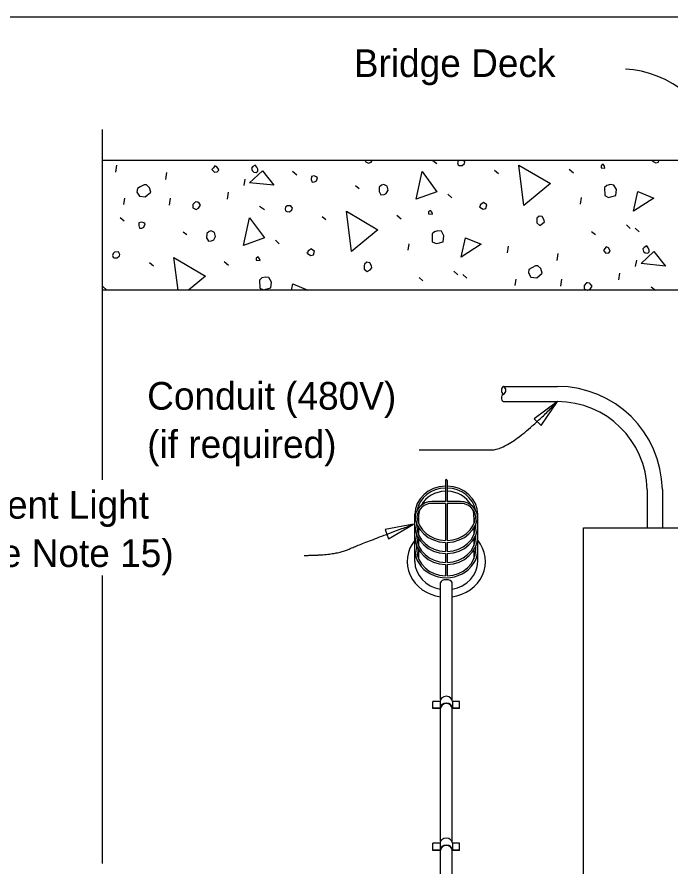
# Model space of a CAD drawing. Extents: x 112544 to 112597.1, y 111084 to 111107.1.
# Drawn here: x 112556.46 to 112560.031, y 111100.721 to 111105.363 of the extents above; entities that cross this region are included whole.
import ezdxf

# ---------------------------------------------------------------- set-up
doc = ezdxf.new("R2010")
doc.units = 0
for name, color, linetype in [('ActivePts-ConstElements', 7, 'Continuous'), ('Dimension', 7, 'Continuous'), ('Lighting', 7, 'Continuous'), ('Miscellaneous', 7, 'Continuous'), ('SteelGirder', 7, 'Continuous'), ('SupstrConc', 7, 'Continuous'), ('TextStructures', 7, 'Continuous')]:
    doc.layers.add(name, color=color, linetype=linetype)

msp = doc.modelspace()

# ---------------------------------------------------------------- linework, layer by layer
at = {"layer": 'ActivePts-ConstElements'}
msp.add_lwpolyline([(112543.9918, 111085.9039), (112574.7797, 111085.9039), (112574.7797, 111105.3634), (112543.9918, 111105.3634)], close=True, dxfattribs=at)
at = {"layer": 'Dimension'}
for points in [[(112556.9271, 111102.8354), (112556.9271, 111104.7499)], [(112556.9271, 111100.7407), (112556.9271, 111102.3132)]]:
    msp.add_lwpolyline(points, dxfattribs=at)
for points in [[(112559.4106, 111103.2627), (112559.2831, 111103.1686), (112559.3212, 111103.1318)], [(112558.6254, 111102.5929), (112558.4697, 111102.5638), (112558.488, 111102.5141)]]:
    msp.add_lwpolyline(points, close=True, dxfattribs=at)
msp.add_ellipse((112559.6704, 111102.7114), major_axis=(-0.1111, -2.3674), ratio=0.464296, start_param=2.502126, end_param=3.141581, dxfattribs=at)
for points in [[(112558.656, 111102.9988), (112558.9418, 111102.9988), (112559.1562, 111102.9988), (112559.4106, 111103.2627)], [(112558.0283, 111102.4231), (112558.1967, 111102.4231), (112558.3447, 111102.4895), (112558.6254, 111102.5929)]]:
    msp.add_open_spline(points, degree=2, dxfattribs=at)
at = {"layer": 'Lighting'}
for p, q in [((112559.1166, 111103.3459), (112559.4106, 111103.3459)), ((112559.1162, 111103.2627), (112559.4106, 111103.2627)), ((112558.7985, 111102.8314), (112558.7985, 111102.7176)), ((112558.8089, 111102.8314), (112558.8089, 111102.7176)), ((112559.9001, 111102.7818), (112559.9001, 111102.5734)), ((112559.9834, 111102.7825), (112559.9834, 111102.5734)), ((112558.7985, 111102.7176), (112558.7256, 111102.7176)), ((112558.7985, 111102.7072), (112558.7256, 111102.7072)), ((112558.7985, 111102.7072), (112558.7985, 111102.504)), ((112558.8819, 111102.7176), (112558.8089, 111102.7176)), ((112558.8089, 111102.7072), (112558.8089, 111102.504)), ((112558.8819, 111102.7072), (112558.8089, 111102.7072)), ((112558.6319, 111102.39), (112558.6319, 111102.6474)), ((112558.9756, 111102.39), (112558.9756, 111102.6474)), ((112558.6423, 111102.5871), (112558.6423, 111102.5947)), ((112558.9652, 111102.5871), (112558.9652, 111102.5947)), ((112558.6423, 111102.5268), (112558.6423, 111102.5344)), ((112558.9652, 111102.5268), (112558.9652, 111102.5344)), ((112558.6423, 111102.4549), (112558.6423, 111102.4741)), ((112558.7985, 111102.4936), (112558.7985, 111102.4437)), ((112558.8089, 111102.4936), (112558.8089, 111102.4437)), ((112558.9652, 111102.4549), (112558.9652, 111102.4741)), ((112558.7985, 111102.4333), (112558.7985, 111102.3834)), ((112558.8089, 111102.4333), (112558.8089, 111102.3834)), ((112558.7985, 111102.373), (112558.7985, 111102.3115)), ((112558.8089, 111102.373), (112558.8089, 111102.3115)), ((112558.7725, 111101.6357), (112558.7725, 111102.2758)), ((112558.8349, 111101.6357), (112558.8349, 111102.2758)), ((112558.7725, 111100.8608), (112558.7725, 111101.5859)), ((112558.8349, 111100.8608), (112558.8349, 111101.5859)), ((112558.7725, 111100.0474), (112558.7725, 111100.811)), ((112558.8349, 111100.0474), (112558.8349, 111100.811))]:
    msp.add_line(p, q, dxfattribs=at)
msp.add_lwpolyline([(112559.6884, 111099.8484), (112559.5529, 111099.8484), (112559.5529, 111102.5734), (112560.5529, 111102.5734), (112560.5529, 111099.8484), (112560.4174, 111099.8484)], dxfattribs=at)
for centre, radius, start, end in [((112559.1281, 111103.325), 0.0238, 119.0026, 240.9973), ((112559.105, 111103.325), 0.0238, 299.0029, 60.997), ((112559.4106, 111102.7731), 0.5729, 0.9435, 90), ((112559.1281, 111103.2833), 0.0238, 119.0027, 240.0206), ((112559.4106, 111102.7731), 0.4896, 1.0206, 90), ((112558.8037, 111102.8314), 0.0052, 0.0584, 180.0007), ((112558.7256, 111102.6239), 0.0937, 90, 180), ((112558.7256, 111102.6239), 0.0833, 90, 172.7392), ((112558.8819, 111102.6239), 0.0937, 0, 90), ((112558.8819, 111102.6239), 0.0833, 7.2613, 90)]:
    msp.add_arc(centre, radius, start, end, dxfattribs=at)
for centre, major_axis, ratio, start_param, end_param in [((112558.8037, 111102.6474), (-0.1718, 0), 0.895384, 4.742653, 7.823718), ((112558.8037, 111102.6474), (-0.1614, 0), 0.888645, 4.744603, 6.130919), ((112558.8037, 111102.6474), (-0.1718, 0), 0.895384, 3.141593, 4.682125), ((112558.8037, 111102.6474), (-0.1614, 0), 0.888645, 3.306024, 4.680175), ((112558.8037, 111102.6474), (-0.1614, 0), 0.888645, 0.090994, 1.538583), ((112558.8037, 111102.6474), (-0.1718, 0), 0.895384, 1.60106, 3.141593), ((112558.8037, 111102.6474), (-0.1614, 0), 0.888645, 1.60301, 3.050599), ((112558.8037, 111102.5871), (-0.1718, 0), 0.895384, 0, 1.540533), ((112558.8037, 111102.5871), (-0.1614, 0), 0.888645, 0.000093, 1.538583), ((112558.8037, 111102.5871), (-0.1718, 0), 0.895384, 1.60106, 3.141593), ((112558.8037, 111102.5871), (-0.1614, 0), 0.888645, 1.60301, 3.141686), ((112558.8037, 111102.5268), (-0.1718, 0), 0.895384, 0, 1.540533), ((112558.8037, 111102.5268), (-0.1614, 0), 0.888645, 0.000093, 1.538583), ((112558.8037, 111102.5268), (-0.1614, 0), 0.888645, 1.60301, 3.141686), ((112558.8037, 111102.5268), (-0.1718, 0), 0.895384, 1.60106, 3.141593), ((112558.8037, 111102.39), (-0.2135, 0), 0.915812, 5.647609, 7.707355), ((112558.8037, 111102.39), (-0.2135, 0), 0.915812, 1.717423, 3.777169), ((112558.8037, 111102.4549), (-0.1718, 0), 0.895384, 0, 3.141593), ((112558.8037, 111102.4549), (-0.1614, 0), 0.888645, 0.000093, 1.538583), ((112558.8037, 111102.4549), (-0.1614, 0), 0.888645, 1.60301, 3.141686), ((112558.8037, 111102.39), (-0.1718, 0), 0.895384, 6.283173, 7.671415), ((112558.8037, 111102.39), (-0.1718, 0), 0.895384, 1.753362, 3.141593), ((112558.8037, 111102.2758), (-0.0312, 0), 0.446008, 3.14248, 6.283159)]:
    msp.add_ellipse(centre, major_axis=major_axis, ratio=ratio, start_param=start_param, end_param=end_param, dxfattribs=at)
at = {"layer": 'Miscellaneous'}
for p, q in [((112556.9999, 111104.5166), (112557.0053, 111104.5543)), ((112558.7305, 111104.5803), (112558.7523, 111104.5642)), ((112557.2723, 111104.4757), (112557.2777, 111104.5134)), ((112557.964, 111104.5213), (112557.9874, 111104.5016)), ((112559.0676, 111104.5271), (112559.0879, 111104.5092)), ((112559.475, 111104.5327), (112559.4984, 111104.5131)), ((112557.7003, 111104.4428), (112557.7064, 111104.4781)), ((112558.3086, 111104.4428), (112558.3282, 111104.4273)), ((112557.0423, 111104.339), (112557.0484, 111104.3743)), ((112557.2916, 111104.3359), (112557.297, 111104.3736)), ((112557.6088, 111104.3691), (112557.6142, 111104.4068)), ((112558.8127, 111104.3967), (112558.8337, 111104.3764)), ((112559.5365, 111104.3421), (112559.5425, 111104.3774)), ((112557.7847, 111104.3309), (112557.8105, 111104.3119)), ((112558.1258, 111104.2747), (112558.1462, 111104.2569)), ((112558.5333, 111104.2804), (112558.5566, 111104.2608)), ((112557.0222, 111104.2689), (112557.0456, 111104.2493)), ((112559.787, 111104.2281), (112559.808, 111104.2078)), ((112557.3668, 111104.1904), (112557.3865, 111104.175)), ((112559.5972, 111104.1928), (112559.6175, 111104.1749)), ((112559.8358, 111104.2101), (112559.8568, 111104.1899)), ((112557.8709, 111104.1443), (112557.8919, 111104.1241)), ((112558.5947, 111104.0898), (112558.6008, 111104.1251)), ((112559.1371, 111104.0747), (112559.1425, 111104.1124)), ((112559.4095, 111104.0338), (112559.4149, 111104.0715)), ((112557.1841, 111104.0224), (112557.2044, 111104.0045)), ((112557.5915, 111104.028), (112557.6149, 111104.0084)), ((112559.8375, 111104.0009), (112559.8436, 111104.0362)), ((112558.8452, 111103.9758), (112558.8662, 111103.9555)), ((112558.8941, 111103.9578), (112558.915, 111103.9375)), ((112559.746, 111103.9272), (112559.7514, 111103.9649)), ((112558.6554, 111103.9404), (112558.6757, 111103.9226)), ((112559.1795, 111103.8971), (112559.1856, 111103.9324)), ((112559.4288, 111103.894), (112559.4342, 111103.9317)), ((112556.9291, 111103.892), (112556.95, 111103.8718)), ((112557.6588, 111103.8718), (112557.659, 111103.8727)), ((112559.9219, 111103.889), (112559.9452, 111103.8718)), ((112558.6528, 111102.6335), (112558.6528, 111102.5966)), ((112558.9547, 111102.6335), (112558.9547, 111102.5966)), ((112558.6528, 111102.5739), (112558.6528, 111102.5362)), ((112558.9547, 111102.5739), (112558.9547, 111102.5362)), ((112558.6528, 111102.5136), (112558.6528, 111102.4759)), ((112558.9547, 111102.5136), (112558.9547, 111102.4759)), ((112558.6528, 111102.4533), (112558.6528, 111102.4041)), ((112558.9547, 111102.4533), (112558.9547, 111102.4041))]:
    msp.add_line(p, q, dxfattribs=at)
for points in [[(112557.7432, 111104.5242), (112557.7531, 111104.5165), (112557.7664, 111104.5149), (112557.7748, 111104.5223), (112557.7746, 111104.5326), (112557.769, 111104.5441), (112557.7609, 111104.5548), (112557.7477, 111104.5461), (112557.7394, 111104.5387), (112557.7432, 111104.5242)], [(112558.3617, 111104.5803), (112558.3616, 111104.5734), (112558.3793, 111104.5652), (112558.3931, 111104.5715), (112558.3993, 111104.5803)], [(112558.8714, 111104.5803), (112558.8679, 111104.5771), (112558.8656, 111104.5661), (112558.8682, 111104.5565)], [(112558.8682, 111104.5565), (112558.8743, 111104.553), (112558.8901, 111104.552), (112558.9027, 111104.5631), (112558.9056, 111104.5717), (112558.8999, 111104.5803)], [(112559.2279, 111104.3345), (112559.2, 111104.5548), (112559.3721, 111104.4534), (112559.2279, 111104.3345)], [(112559.649, 111104.5405), (112559.6702, 111104.5384), (112559.6676, 111104.5481), (112559.6596, 111104.5589), (112559.6488, 111104.5508), (112559.649, 111104.5405)], [(112559.9295, 111104.5803), (112559.9291, 111104.5768), (112559.9282, 111104.5803)], [(112559.9291, 111104.5768), (112559.9475, 111104.5662), (112559.962, 111104.57), (112559.9647, 111104.5803)], [(112557.5242, 111104.5302), (112557.5384, 111104.5159), (112557.5535, 111104.5174), (112557.5613, 111104.5272), (112557.56, 111104.5321), (112557.5513, 111104.5453), (112557.5397, 111104.5499), (112557.5319, 111104.5401), (112557.5242, 111104.5302)], [(112557.7298, 111104.4585), (112557.8002, 111104.524), (112557.8628, 111104.445), (112557.7298, 111104.4585)], [(112558.6391, 111104.3683), (112558.6712, 111104.5192), (112558.7524, 111104.409), (112558.6391, 111104.3683)], [(112558.0667, 111104.4763), (112558.0705, 111104.4618), (112558.0833, 111104.4626), (112558.0947, 111104.4683), (112558.1005, 111104.4854), (112558.0937, 111104.4913), (112558.0821, 111104.496), (112558.0676, 111104.4921), (112558.0667, 111104.4763)], [(112557.1145, 111104.4075), (112557.1282, 111104.3853), (112557.1604, 111104.381), (112557.1897, 111104.407), (112557.1833, 111104.4311), (112557.166, 111104.4472), (112557.1533, 111104.4464), (112557.1328, 111104.4357), (112557.1172, 111104.4264), (112557.1145, 111104.4075)], [(112558.4379, 111104.4334), (112558.4365, 111104.4098), (112558.4465, 111104.3917), (112558.464, 111104.3938), (112558.4755, 111104.3995), (112558.4861, 111104.4179), (112558.4803, 111104.4396), (112558.4625, 111104.4478), (112558.4505, 111104.4446), (112558.4379, 111104.4334)], [(112559.6678, 111104.4317), (112559.6691, 111104.388), (112559.6899, 111104.3781), (112559.702, 111104.3813), (112559.7285, 111104.3884), (112559.7328, 111104.4206), (112559.7185, 111104.4453), (112559.6996, 111104.448), (112559.6803, 111104.4428), (112559.6678, 111104.4317)], [(112559.8264, 111104.3034), (112559.8494, 111104.4105), (112559.9368, 111104.3743), (112559.8264, 111104.3034)], [(112557.4201, 111104.3393), (112557.4198, 111104.3211), (112557.4375, 111104.3129), (112557.4514, 111104.3192), (112557.4626, 111104.3352), (112557.4545, 111104.3459), (112557.4478, 111104.3519), (112557.4368, 111104.3541), (112557.432, 111104.3528), (112557.4201, 111104.3393)], [(112557.9264, 111104.3041), (112557.9326, 111104.3006), (112557.9483, 111104.2997), (112557.9609, 111104.3108), (112557.9638, 111104.3193), (112557.9551, 111104.3325), (112557.9345, 111104.3322), (112557.9261, 111104.3248), (112557.9239, 111104.3138), (112557.9264, 111104.3041)], [(112558.9873, 111104.3244), (112559.0057, 111104.3138), (112559.0202, 111104.3177), (112559.0253, 111104.3372), (112559.0063, 111104.3502), (112558.998, 111104.3428), (112558.9889, 111104.3378), (112558.9873, 111104.3244), (112558.9861, 111104.3292)], [(112558.2861, 111104.0822), (112558.2582, 111104.3024), (112558.4303, 111104.201), (112558.2861, 111104.0822)], [(112558.7072, 111104.2882), (112558.7284, 111104.2861), (112558.7259, 111104.2958), (112558.7178, 111104.3065), (112558.707, 111104.2985), (112558.7072, 111104.2882)], [(112559.2977, 111104.2575), (112559.2974, 111104.2393), (112559.3141, 111104.2256), (112559.3297, 111104.235), (112559.3398, 111104.2454), (112559.3366, 111104.2575), (112559.3272, 111104.2731), (112559.3108, 111104.2765), (112559.2982, 111104.2654), (112559.2977, 111104.2575)], [(112557.1249, 111104.224), (112557.1288, 111104.2095), (112557.1415, 111104.2103), (112557.1529, 111104.2159), (112557.1587, 111104.233), (112557.1519, 111104.239), (112557.1403, 111104.2436), (112557.1258, 111104.2397), (112557.1249, 111104.224)], [(112557.6973, 111104.1159), (112557.7294, 111104.2669), (112557.8107, 111104.1567), (112557.6973, 111104.1159)], [(112557.4961, 111104.1811), (112557.4947, 111104.1574), (112557.5047, 111104.1394), (112557.5223, 111104.1415), (112557.5337, 111104.1471), (112557.5443, 111104.1655), (112557.5385, 111104.1872), (112557.5208, 111104.1954), (112557.5087, 111104.1922), (112557.4961, 111104.1811)], [(112558.726, 111104.1793), (112558.7273, 111104.1357), (112558.7481, 111104.1257), (112558.7602, 111104.129), (112558.7868, 111104.1361), (112558.7911, 111104.1683), (112558.7767, 111104.1929), (112558.7579, 111104.1956), (112558.7385, 111104.1905), (112558.726, 111104.1793)], [(112558.8846, 111104.051), (112558.9077, 111104.1581), (112558.995, 111104.122), (112558.8846, 111104.051)], [(112558.0456, 111104.0721), (112558.0639, 111104.0615), (112558.0784, 111104.0653), (112558.0836, 111104.0848), (112558.0645, 111104.0979), (112558.0562, 111104.0904), (112558.0472, 111104.0854), (112558.0456, 111104.0721), (112558.0443, 111104.0769)], [(112559.6614, 111104.0883), (112559.6756, 111104.074), (112559.6907, 111104.0755), (112559.6985, 111104.0853), (112559.6972, 111104.0901), (112559.6885, 111104.1033), (112559.6769, 111104.108), (112559.6691, 111104.0982), (112559.6614, 111104.0883)], [(112559.8804, 111104.0823), (112559.8903, 111104.0746), (112559.9036, 111104.073), (112559.912, 111104.0804), (112559.9118, 111104.0907), (112559.9062, 111104.1022), (112559.8981, 111104.1129), (112559.8849, 111104.1042), (112559.8766, 111104.0968), (112559.8804, 111104.0823)], [(112556.9847, 111104.0518), (112556.9908, 111104.0483), (112557.0066, 111104.0473), (112557.0191, 111104.0584), (112557.022, 111104.067), (112557.0133, 111104.0802), (112556.9927, 111104.0798), (112556.9843, 111104.0724), (112556.9821, 111104.0615), (112556.9847, 111104.0518)], [(112557.339, 111103.8718), (112557.3164, 111104.0501), (112557.4885, 111103.9487), (112557.3953, 111103.8718)], [(112557.7654, 111104.0358), (112557.7867, 111104.0338), (112557.7841, 111104.0434), (112557.776, 111104.0542), (112557.7652, 111104.0461), (112557.7654, 111104.0358)], [(112559.867, 111104.0166), (112559.9374, 111104.0821), (112560, 111104.0031), (112559.867, 111104.0166)], [(112558.356, 111104.0051), (112558.3557, 111103.9869), (112558.3723, 111103.9733), (112558.3879, 111103.9826), (112558.398, 111103.9931), (112558.3948, 111104.0052), (112558.3854, 111104.0208), (112558.369, 111104.0241), (112558.3564, 111104.013), (112558.356, 111104.0051)], [(112559.2517, 111103.9656), (112559.2654, 111103.9434), (112559.2976, 111103.9391), (112559.3269, 111103.9651), (112559.3205, 111103.9892), (112559.3032, 111104.0053), (112559.2905, 111104.0045), (112559.27, 111103.9938), (112559.2544, 111103.9845), (112559.2517, 111103.9656)], [(112557.7842, 111103.927), (112557.7856, 111103.8833), (112557.8063, 111103.8734), (112557.8184, 111103.8766), (112557.845, 111103.8837), (112557.8493, 111103.9159), (112557.8349, 111103.9406), (112557.8161, 111103.9433), (112557.7968, 111103.9381), (112557.7842, 111103.927)], [(112557.9586, 111103.8718), (112557.9659, 111103.9058), (112558.048, 111103.8718)], [(112559.5765, 111103.8718), (112559.5886, 111103.8773), (112559.5998, 111103.8932), (112559.5917, 111103.904), (112559.585, 111103.91), (112559.574, 111103.9122), (112559.5692, 111103.9109), (112559.5573, 111103.8974)], [(112559.5573, 111103.8974), (112559.557, 111103.8792), (112559.5729, 111103.8718)]]:
    msp.add_lwpolyline(points, dxfattribs=at)
for start_param, end_param in [(1.605229, 2.691201), (0.45306, 1.536364), (2.896336, 3.176025), (6.248753, 6.522968)]:
    msp.add_ellipse((112558.8037, 111102.6382), major_axis=(0.151, 0), ratio=0.895384, start_param=start_param, end_param=end_param, dxfattribs=at)
at = {"layer": 'SteelGirder'}
for p, q in [((112558.7702, 111101.6256), (112558.7308, 111101.6256)), ((112558.7308, 111101.5859), (112558.7308, 111101.6256)), ((112558.7702, 111101.5882), (112558.7308, 111101.5882)), ((112558.7725, 111101.5859), (112558.7308, 111101.5859)), ((112558.7702, 111101.6256), (112558.7702, 111101.5882)), ((112558.8766, 111101.5859), (112558.8349, 111101.5859)), ((112558.8766, 111101.6256), (112558.8372, 111101.6256)), ((112558.8372, 111101.6256), (112558.8372, 111101.5882)), ((112558.8766, 111101.5882), (112558.8372, 111101.5882)), ((112558.8766, 111101.5859), (112558.8766, 111101.6256)), ((112558.7702, 111100.8506), (112558.7308, 111100.8506)), ((112558.7308, 111100.811), (112558.7308, 111100.8506)), ((112558.7702, 111100.8507), (112558.7702, 111100.8133)), ((112558.8766, 111100.8506), (112558.8372, 111100.8506)), ((112558.8372, 111100.8506), (112558.8372, 111100.8133)), ((112558.8766, 111100.811), (112558.8766, 111100.8506)), ((112558.7702, 111100.8133), (112558.7308, 111100.8133)), ((112558.7725, 111100.811), (112558.7308, 111100.811)), ((112558.8766, 111100.811), (112558.8349, 111100.811)), ((112558.8766, 111100.8133), (112558.8372, 111100.8133))]:
    msp.add_line(p, q, dxfattribs=at)
for centre, major_axis, ratio, end_param in [((112558.8037, 111101.6256), (-0.0335, 0), 0.830773, 6.282753), ((112558.8037, 111101.5882), (-0.0335, 0), 0.830773, 6.282753), ((112558.8037, 111101.5859), (-0.0312, 0), 0.892016, 6.283768), ((112558.8037, 111100.8506), (-0.0335, 0), 0.830773, 6.282753), ((112558.8037, 111100.8133), (-0.0335, 0), 0.830773, 6.282753), ((112558.8037, 111100.811), (-0.0312, 0), 0.892016, 6.283768)]:
    msp.add_ellipse(centre, major_axis=major_axis, ratio=ratio, start_param=3.141593, end_param=end_param, dxfattribs=at)
at = {"layer": 'SupstrConc'}
for p, q in [((112561.9699, 111104.5803), (112556.9271, 111104.5803)), ((112561.9699, 111103.8718), (112556.9271, 111103.8718))]:
    msp.add_line(p, q, dxfattribs=at)

# ---------------------------------------------------------------- texts
at = {"layer": 'Dimension'}
for s, p in [('Conduit (480V)', (112557.1706, 111103.2188)), ('(if required)', (112557.1706, 111102.9548)), ('Incandescent Light', (112555.4835, 111102.6236)), ('fixture (see Note 15)', (112555.4835, 111102.3596))]:
    msp.add_text(s, height=0.1512, dxfattribs=at).set_placement(p)
at = {"layer": 'TextStructures'}
msp.add_text('Bridge Deck', height=0.1512, dxfattribs=at).set_placement((112558.2987, 111105.0358))

doc.saveas('drawing.dxf')
